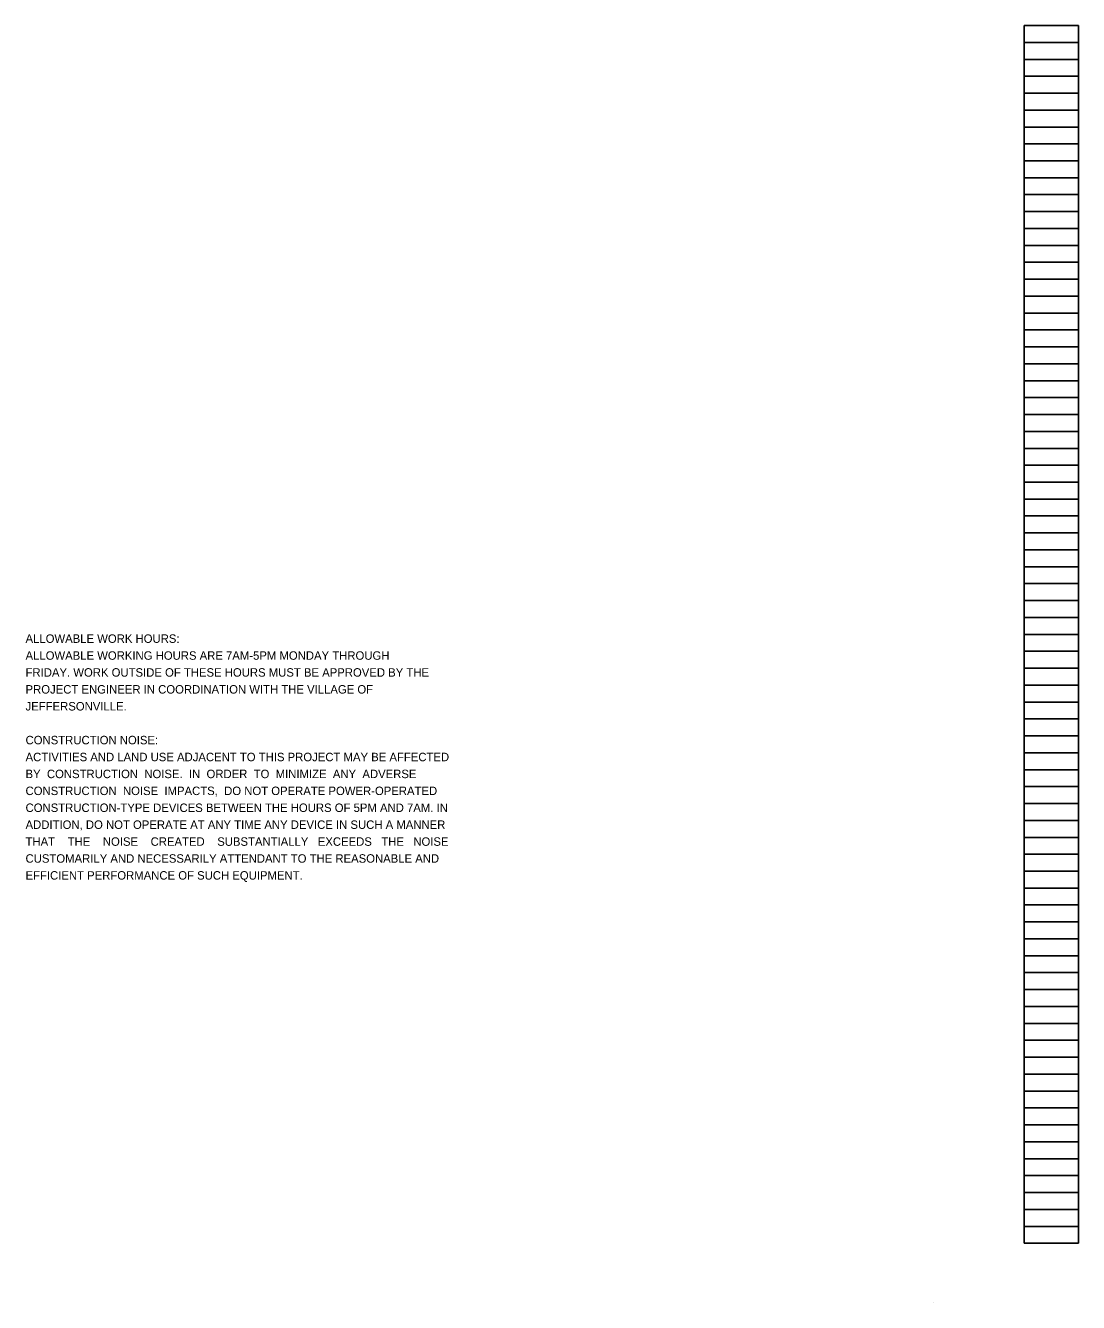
# Model space of a CAD drawing. Extents: x 37613.4 to 37668.4, y 18853.7 to 18946.8.
# Drawn here: x 37621.37 to 37638.8, y 18925.61 to 18946.75 of the extents above; entities that cross this region are included whole.
import ezdxf

# ---------------------------------------------------------------- set-up
doc = ezdxf.new("R2010")
doc.units = 0
doc.layers.add('SH_Data', color=7, linetype='Continuous')
doc.layers.add('SH_Text', color=7, linetype='Continuous')

msp = doc.modelspace()

# ---------------------------------------------------------------- linework, layer by layer
at = {"layer": 'SH_Data'}
for p, q in [((37637.901, 18926.595), (37637.901, 18946.755)), ((37637.901, 18946.755), (37638.801, 18946.755)), ((37638.801, 18926.595), (37638.801, 18946.755)), ((37637.901, 18946.475), (37638.801, 18946.475)), ((37637.901, 18946.195), (37638.801, 18946.195)), ((37637.901, 18945.915), (37638.801, 18945.915)), ((37637.901, 18945.635), (37638.801, 18945.635)), ((37637.901, 18945.355), (37638.801, 18945.355)), ((37637.901, 18945.075), (37638.801, 18945.075)), ((37637.901, 18944.795), (37638.801, 18944.795)), ((37637.901, 18944.515), (37638.801, 18944.515)), ((37637.901, 18944.235), (37638.801, 18944.235)), ((37637.901, 18943.955), (37638.801, 18943.955)), ((37637.901, 18943.675), (37638.801, 18943.675)), ((37637.901, 18943.395), (37638.801, 18943.395)), ((37637.901, 18943.115), (37638.801, 18943.115)), ((37637.901, 18942.835), (37638.801, 18942.835)), ((37637.901, 18942.555), (37638.801, 18942.555)), ((37637.901, 18942.275), (37638.801, 18942.275)), ((37637.901, 18941.995), (37638.801, 18941.995)), ((37637.901, 18941.715), (37638.801, 18941.715)), ((37637.901, 18941.435), (37638.801, 18941.435)), ((37637.901, 18941.155), (37638.801, 18941.155)), ((37637.901, 18940.875), (37638.801, 18940.875)), ((37637.901, 18940.595), (37638.801, 18940.595)), ((37637.901, 18940.315), (37638.801, 18940.315)), ((37637.901, 18940.035), (37638.801, 18940.035)), ((37637.901, 18939.755), (37638.801, 18939.755)), ((37637.901, 18939.475), (37638.801, 18939.475)), ((37637.901, 18939.195), (37638.801, 18939.195)), ((37637.901, 18938.915), (37638.801, 18938.915)), ((37637.901, 18938.635), (37638.801, 18938.635)), ((37637.901, 18938.355), (37638.801, 18938.355)), ((37637.901, 18938.075), (37638.801, 18938.075)), ((37637.901, 18937.795), (37638.801, 18937.795)), ((37637.901, 18937.515), (37638.801, 18937.515)), ((37637.901, 18937.235), (37638.801, 18937.235)), ((37637.901, 18936.955), (37638.801, 18936.955)), ((37637.901, 18936.675), (37638.801, 18936.675)), ((37637.901, 18936.395), (37638.801, 18936.395)), ((37637.901, 18936.115), (37638.801, 18936.115)), ((37637.901, 18935.835), (37638.801, 18935.835)), ((37637.901, 18935.555), (37638.801, 18935.555)), ((37637.901, 18935.275), (37638.801, 18935.275)), ((37637.901, 18934.995), (37638.801, 18934.995)), ((37637.901, 18934.715), (37638.801, 18934.715)), ((37637.901, 18934.435), (37638.801, 18934.435)), ((37637.901, 18934.155), (37638.801, 18934.155)), ((37637.901, 18933.875), (37638.801, 18933.875)), ((37637.901, 18933.595), (37638.801, 18933.595)), ((37637.901, 18933.315), (37638.801, 18933.315)), ((37637.901, 18933.035), (37638.801, 18933.035)), ((37637.901, 18932.755), (37638.801, 18932.755)), ((37637.901, 18932.475), (37638.801, 18932.475)), ((37637.901, 18932.195), (37638.801, 18932.195)), ((37637.901, 18931.915), (37638.801, 18931.915)), ((37637.901, 18931.635), (37638.801, 18931.635)), ((37637.901, 18931.355), (37638.801, 18931.355)), ((37637.901, 18931.075), (37638.801, 18931.075)), ((37637.901, 18930.795), (37638.801, 18930.795)), ((37637.901, 18930.515), (37638.801, 18930.515)), ((37637.901, 18930.235), (37638.801, 18930.235)), ((37637.901, 18929.955), (37638.801, 18929.955)), ((37637.901, 18929.675), (37638.801, 18929.675)), ((37637.901, 18929.395), (37638.801, 18929.395)), ((37637.901, 18929.115), (37638.801, 18929.115)), ((37637.901, 18928.835), (37638.801, 18928.835)), ((37637.901, 18928.555), (37638.801, 18928.555)), ((37637.901, 18928.275), (37638.801, 18928.275)), ((37637.901, 18927.995), (37638.801, 18927.995)), ((37637.901, 18927.715), (37638.801, 18927.715)), ((37637.901, 18927.435), (37638.801, 18927.435)), ((37637.901, 18927.155), (37638.801, 18927.155)), ((37637.901, 18926.875), (37638.801, 18926.875)), ((37637.901, 18926.595), (37638.801, 18926.595)), ((37636.401, 18925.615), (37636.401, 18925.615))]:
    msp.add_line(p, q, dxfattribs=at)

# ---------------------------------------------------------------- texts
at = {"layer": 'SH_Text'}
for s, p in [('ALLOWABLE WORK HOURS:', (37621.374, 18936.535)), ('ALLOWABLE WORKING HOURS ARE 7AM-5PM MONDAY THROUGH ', (37621.374, 18936.255)), ('FRIDAY. WORK OUTSIDE OF THESE HOURS MUST BE APPROVED BY THE ', (37621.374, 18935.975)), ('PROJECT ENGINEER IN COORDINATION WITH THE VILLAGE OF ', (37621.374, 18935.695)), ('JEFFERSONVILLE.', (37621.374, 18935.415)), ('CONSTRUCTION NOISE:', (37621.374, 18934.855)), ('ACTIVITIES AND LAND USE ADJACENT TO THIS PROJECT MAY BE AFFECTED', (37621.374, 18934.575)), ('BY  CONSTRUCTION  NOISE.  IN  ORDER  TO  MINIMIZE  ANY  ADVERSE', (37621.374, 18934.295)), ('CONSTRUCTION  NOISE  IMPACTS,  DO NOT OPERATE POWER-OPERATED', (37621.374, 18934.015)), ('CONSTRUCTION-TYPE DEVICES BETWEEN THE HOURS OF 5PM AND 7AM. IN', (37621.374, 18933.735)), ('ADDITION, DO NOT OPERATE AT ANY TIME ANY DEVICE IN SUCH A MANNER', (37621.374, 18933.455)), ('THAT    THE    NOISE    CREATED    SUBSTANTIALLY   EXCEEDS   THE   NOISE', (37621.374, 18933.175)), ('CUSTOMARILY AND NECESSARILY ATTENDANT TO THE REASONABLE AND', (37621.374, 18932.895)), ('EFFICIENT PERFORMANCE OF SUCH EQUIPMENT.', (37621.374, 18932.615))]:
    msp.add_text(s, height=0.14, dxfattribs=at).set_placement(p)

doc.saveas('drawing.dxf')
